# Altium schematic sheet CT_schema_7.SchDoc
size 266 x 267 mm
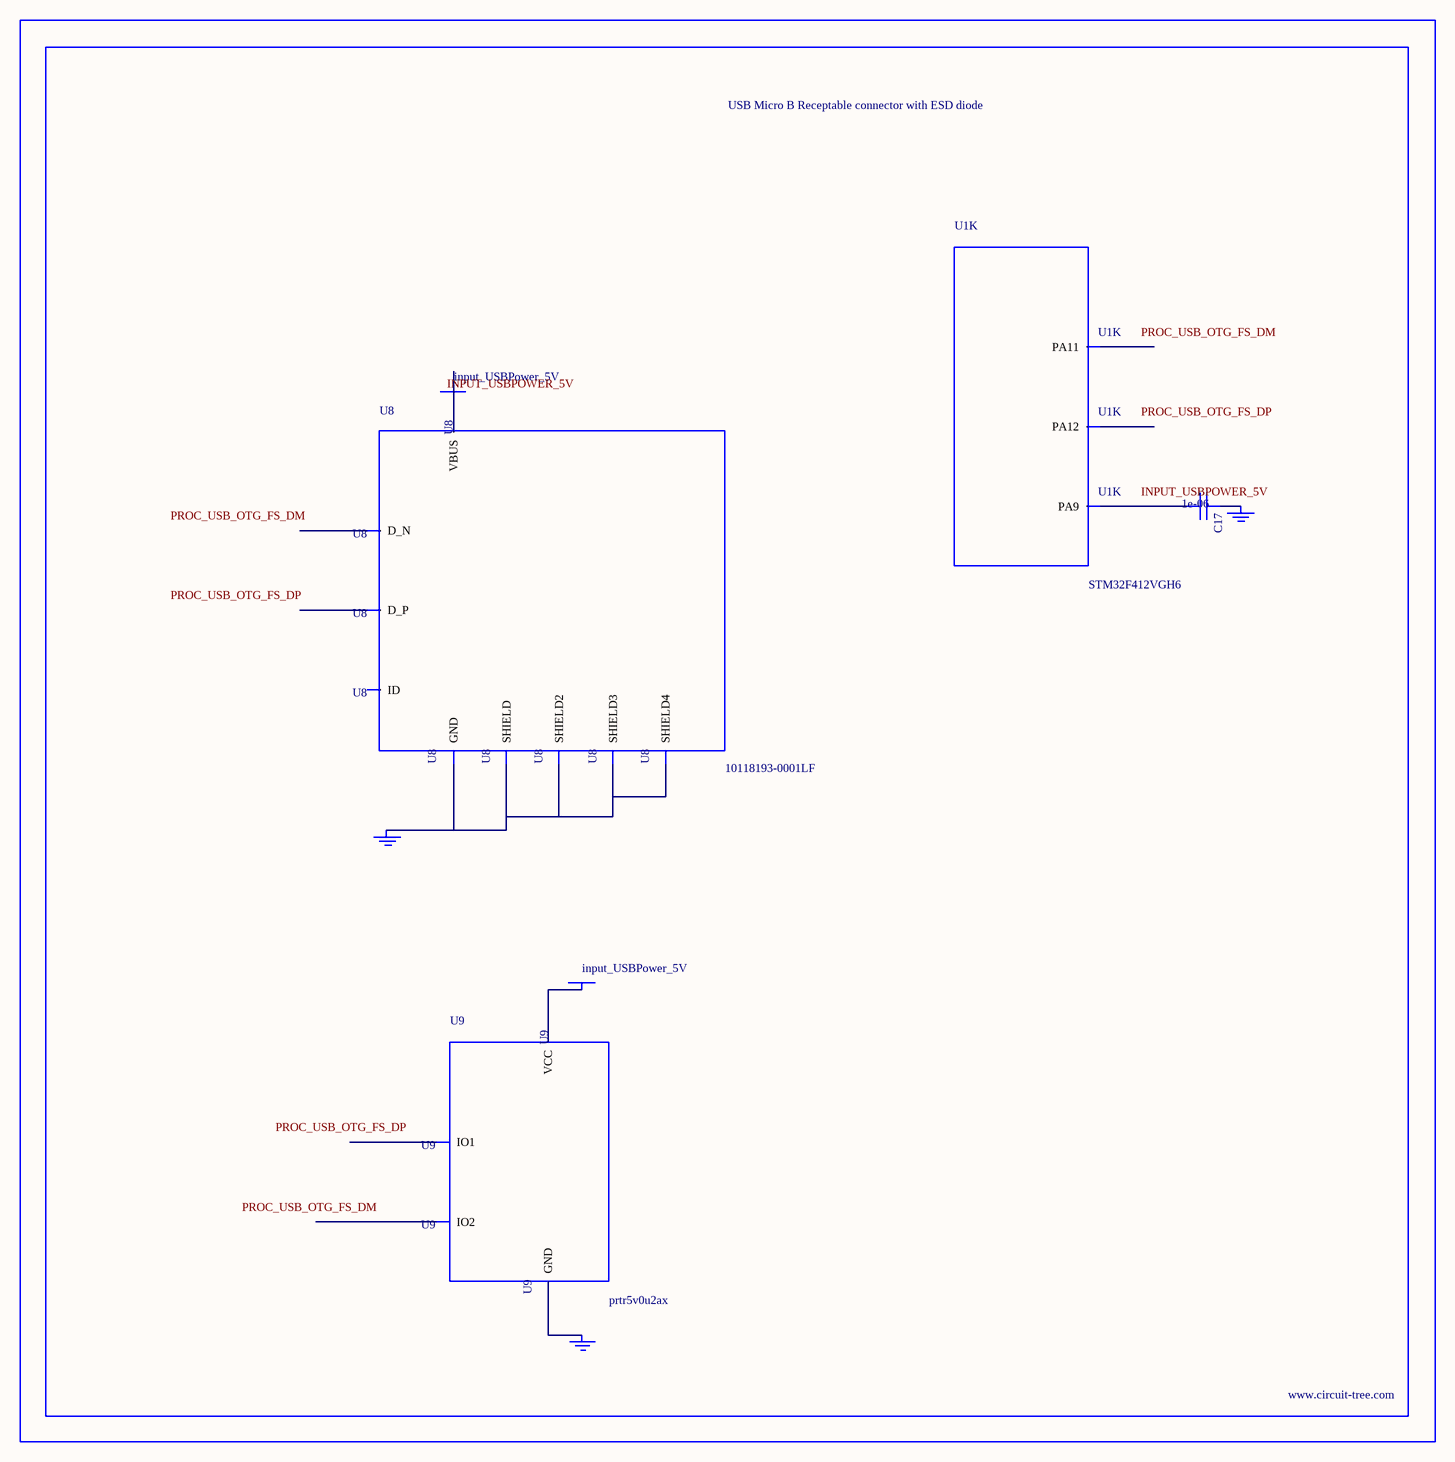
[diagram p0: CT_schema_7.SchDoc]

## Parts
BORDER6  (no value)
C17  1e-06  [C0603]
GND_INSTANCE_6_0  (no value)
GND_INSTANCE_6_1  (no value)
GND_INSTANCE_6_2  (no value)
POWER_INSTANCE_6_0  input_USBPower_5V
POWER_INSTANCE_6_1  input_USBPower_5V
U1  STM32F412VGH6  [UFBGA100]  (part K of 11)
U8  10118193-0001LF  [FCI_10118193-0001LF]
U9  prtr5v0u2ax  [SOT143B]

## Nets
NetC17_1: C17.1 GND_INSTANCE_6_1.0(GND)
NetC17_2: C17.2 U1.D10(PA9)
NetGND_INSTANCE_6_0_0: GND_INSTANCE_6_0.0(GND) U8.5(GND) U8.6(SHIELD) U8.7(SHIELD2) U8.8(SHIELD3) U8.9(SHIELD4)
NetGND_INSTANCE_6_2_0: GND_INSTANCE_6_2.0(GND) U9.1(GND)
NetPOWER_INSTANCE_6_0_0: POWER_INSTANCE_6_0.0(PWR) U8.1(VBUS)
NetPOWER_INSTANCE_6_1_0: POWER_INSTANCE_6_1.0(PWR) U9.4(VCC)

Not connected (* = marked no-connect by the designer): U1 A12(PA12) B12(PA11); U8 2(D_N) 3(D_P) 4(ID); U9 2(IO1) 3(IO2)

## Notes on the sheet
- Labels drawn without touching a wire or pin: INPUT_USBPOWER_5V, PROC_USB_OTG_FS_DM, PROC_USB_OTG_FS_DP

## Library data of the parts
BORDER6 = BORDER_PAGE6
C17 = C0603C105K3RACTU
GND_INSTANCE_6_0-GND_INSTANCE_6_2 = GND
POWER_INSTANCE_6_0 POWER_INSTANCE_6_1 = PWR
